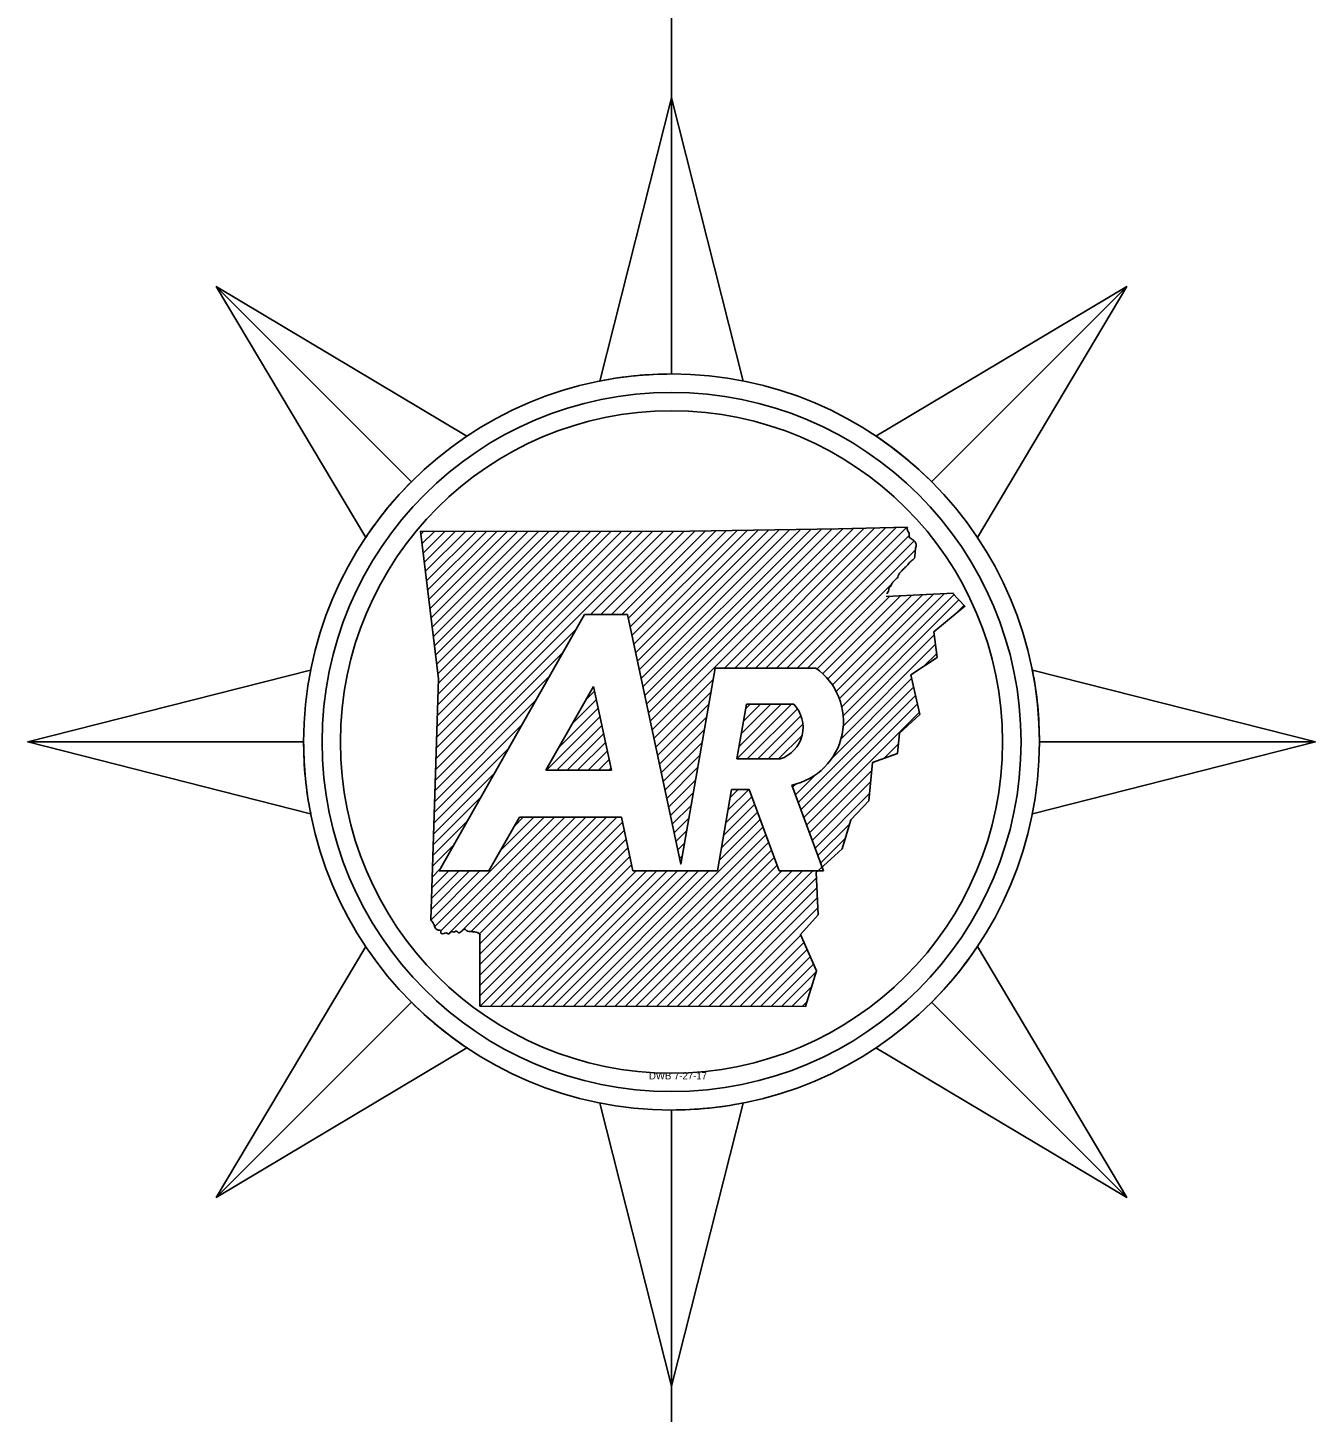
# Model space of a CAD drawing. Extents: x 155 to 3386, y 68 to 2138.
# Drawn here: x 2378.1 to 2518.1, y 610.2 to 760.7 of the extents above; entities that cross this region are included whole.
import ezdxf

# ---------------------------------------------------------------- set-up
doc = ezdxf.new("R2010")
doc.units = 0
doc.layers.add('R_Draft', color=7, linetype='Continuous')

msp = doc.modelspace()

# ---------------------------------------------------------------- linework, layer by layer
at = {"layer": 'R_Draft'}
for p, q in [((2448.14, 885.31), (2448.14, 727.4)), ((2448.14, 753.03), (2440.35, 722.26)), ((2448.14, 723.03), (2448.14, 753.03)), ((2398.64, 732.53), (2419.85, 711.31)), ((2419.85, 711.31), (2398.64, 732.53)), ((2398.64, 732.53), (2414.89, 705.26)), ((2497.63, 732.53), (2470.37, 716.28)), ((2476.42, 711.31), (2497.63, 732.53)), ((2476.42, 711.31), (2497.63, 732.53)), ((2420.87, 705.57), (2421.22, 705.93)), ((2421, 704.57), (2422.35, 705.92)), ((2421.12, 703.56), (2423.48, 705.92)), ((2421.25, 702.55), (2424.62, 705.92)), ((2421.37, 701.55), (2425.75, 705.92)), ((2421.5, 700.54), (2426.88, 705.92)), ((2421.62, 699.54), (2428.01, 705.92)), ((2421.75, 698.53), (2429.14, 705.92)), ((2421.87, 697.52), (2430.27, 705.92)), ((2422, 696.52), (2431.4, 705.92)), ((2422.12, 695.51), (2432.53, 705.92)), ((2422.25, 694.51), (2433.66, 705.92)), ((2422.37, 693.5), (2434.79, 705.92)), ((2422.5, 692.49), (2435.92, 705.92)), ((2422.54, 681.22), (2447.26, 705.94)), ((2422.58, 682.39), (2446.12, 705.94)), ((2422.62, 683.56), (2444.99, 705.93)), ((2422.62, 691.49), (2437.05, 705.92)), ((2422.65, 684.73), (2443.86, 705.93)), ((2422.69, 685.9), (2442.72, 705.93)), ((2422.73, 687.07), (2441.59, 705.93)), ((2422.75, 690.48), (2438.19, 705.92)), ((2422.77, 688.24), (2440.46, 705.92)), ((2422.81, 689.41), (2439.32, 705.92)), ((2439.34, 696.89), (2448.39, 705.94)), ((2440.47, 696.89), (2449.53, 705.94)), ((2441.6, 696.89), (2450.67, 705.95)), ((2442.73, 696.89), (2451.82, 705.97)), ((2443.44, 696.46), (2452.97, 705.99)), ((2443.64, 695.53), (2454.11, 706.01)), ((2443.84, 694.6), (2455.26, 706.02)), ((2444.04, 693.66), (2456.41, 706.04)), ((2444.23, 692.73), (2457.56, 706.06)), ((2444.43, 691.8), (2458.71, 706.08)), ((2444.63, 690.87), (2459.86, 706.1)), ((2444.83, 689.94), (2461.01, 706.11)), ((2445.03, 689.01), (2462.16, 706.13)), ((2445.23, 688.07), (2463.31, 706.15)), ((2445.43, 687.14), (2464.46, 706.17)), ((2445.63, 686.21), (2465.61, 706.19)), ((2445.83, 685.28), (2466.76, 706.21)), ((2446.03, 684.35), (2467.92, 706.23)), ((2453.89, 691.07), (2469.08, 706.26)), ((2455.02, 691.07), (2470.23, 706.29)), ((2456.15, 691.07), (2471.39, 706.31)), ((2457.28, 691.07), (2472.55, 706.34)), ((2458.41, 691.07), (2473.71, 706.37)), ((2459.55, 691.07), (2473.96, 705.49)), ((2460.68, 691.07), (2474.51, 704.9)), ((2461.81, 691.07), (2474.65, 703.92)), ((2462.94, 691.07), (2472.07, 700.2)), ((2463.97, 690.97), (2471.85, 698.85)), ((2464.59, 690.46), (2473.04, 698.91)), ((2465.14, 689.88), (2474.23, 698.97)), ((2465.63, 689.23), (2475.43, 699.03)), ((2466.05, 688.52), (2476.62, 699.1)), ((2466.39, 687.74), (2477.81, 699.16)), ((2466.65, 686.87), (2478.89, 699.1)), ((2466.81, 685.89), (2479.41, 698.5)), ((2422.87, 669.02), (2438.66, 696.89)), ((2438.66, 696.89), (2443.35, 696.89)), ((2478.91, 696.86), (2479.94, 697.89)), ((2422.5, 680.05), (2437.76, 695.31)), ((2466.81, 684.76), (2476.71, 694.67)), ((2422.46, 678.88), (2436.29, 692.71)), ((2466.58, 683.39), (2476.84, 693.66)), ((2475.58, 691.27), (2476.97, 692.66)), ((2452.87, 691.07), (2463.83, 691.07)), ((2518.14, 683.03), (2487.37, 690.82)), ((2422.42, 677.71), (2434.81, 690.1)), ((2446.23, 683.41), (2452.65, 689.83)), ((2465.59, 681.28), (2474.24, 689.92)), ((2434.48, 679.96), (2439.65, 689.07)), ((2438.84, 687.65), (2439.75, 688.57)), ((2446.43, 682.48), (2452.41, 688.46)), ((2461.9, 676.46), (2474.45, 689)), ((2462.21, 675.64), (2474.66, 688.08)), ((2422.38, 676.54), (2433.33, 687.49)), ((2435.89, 682.44), (2440.15, 686.7)), ((2437.37, 685.05), (2439.95, 687.63)), ((2446.63, 681.55), (2452.17, 687.09)), ((2455.25, 681.19), (2461.2, 687.14)), ((2455.48, 682.55), (2460.07, 687.14)), ((2455.72, 683.92), (2458.94, 687.14)), ((2455.96, 685.29), (2457.81, 687.14)), ((2456.2, 686.66), (2456.68, 687.14)), ((2456.28, 687.14), (2461.43, 687.14)), ((2456.38, 681.19), (2461.83, 686.64)), ((2462.52, 674.81), (2474.87, 687.16)), ((2422.34, 675.37), (2431.86, 684.88)), ((2434.54, 679.96), (2440.35, 685.77)), ((2435.67, 679.96), (2440.55, 684.84)), ((2446.83, 680.62), (2451.93, 685.72)), ((2457.51, 681.19), (2462.21, 685.89)), ((2458.64, 681.19), (2462.42, 684.97)), ((2462.82, 673.98), (2475.08, 686.24)), ((2436.8, 679.96), (2440.75, 683.91)), ((2447.03, 679.69), (2451.69, 684.35)), ((2459.78, 681.19), (2462.33, 683.74)), ((2378.14, 683.03), (2408.14, 683.03)), ((2408.14, 683.03), (2378.14, 683.03)), ((2378.14, 683.03), (2408.9, 675.24)), ((2422.3, 674.2), (2430.38, 682.27)), ((2437.93, 679.96), (2440.95, 682.97)), ((2439.06, 679.96), (2441.15, 682.04)), ((2447.23, 678.75), (2451.46, 682.98)), ((2471.22, 681.25), (2472.8, 682.83)), ((2488.14, 683.03), (2518.14, 683.03)), ((2488.14, 683.03), (2518.14, 683.03)), ((2440.19, 679.96), (2441.35, 681.11)), ((2447.43, 677.82), (2451.22, 681.61)), ((2447.63, 676.89), (2450.98, 680.24)), ((2455.24, 681.19), (2459.94, 681.19)), ((2422.27, 673.03), (2428.9, 679.66)), ((2434.48, 679.96), (2441.6, 679.96)), ((2441.33, 679.96), (2441.55, 680.18)), ((2447.82, 675.96), (2450.74, 678.87)), ((2461.6, 677.29), (2463.75, 679.44)), ((2463.13, 673.16), (2469.91, 679.94)), ((2448.02, 675.03), (2450.5, 677.5)), ((2454.27, 675.62), (2456.53, 677.88)), ((2454.51, 676.99), (2455.4, 677.88)), ((2456.57, 677.88), (2454.67, 677.88)), ((2459.84, 669.02), (2456.57, 677.88)), ((2461.21, 678.35), (2464.66, 669.02)), ((2461.29, 678.11), (2461.64, 678.46)), ((2463.43, 672.33), (2469.79, 678.69)), ((2463.74, 671.5), (2469.66, 677.43)), ((2422.23, 671.86), (2427.43, 677.06)), ((2448.22, 674.09), (2450.26, 676.13)), ((2453.8, 672.88), (2457.17, 676.25)), ((2454.03, 674.25), (2456.86, 677.08)), ((2422.19, 670.69), (2425.95, 674.45)), ((2422.39, 662.97), (2434.29, 674.86)), ((2423.07, 662.51), (2435.42, 674.86)), ((2423.88, 662.19), (2436.55, 674.86)), ((2425.22, 662.41), (2437.68, 674.86)), ((2426.37, 662.43), (2438.81, 674.86)), ((2427.26, 662.18), (2439.94, 674.86)), ((2427.3, 659.96), (2442.2, 674.86)), ((2427.3, 661.09), (2441.07, 674.86)), ((2427.3, 658.83), (2442.8, 674.33)), ((2431.6, 674.86), (2428.29, 669.02)), ((2429.57, 671.28), (2433.15, 674.86)), ((2431.05, 673.89), (2432.02, 674.86)), ((2442.69, 674.86), (2431.6, 674.86)), ((2448.42, 673.16), (2450.02, 674.76)), ((2453.32, 670.14), (2457.78, 674.6)), ((2453.56, 671.51), (2457.47, 675.42)), ((2427.31, 657.7), (2443, 673.4)), ((2438.62, 654.31), (2458.08, 673.77)), ((2439.75, 654.31), (2458.39, 672.95)), ((2448.62, 672.23), (2449.78, 673.39)), ((2464.04, 670.68), (2467.51, 674.15)), ((2422.15, 669.52), (2424.47, 671.84)), ((2427.31, 656.57), (2443.2, 672.46)), ((2427.31, 655.44), (2443.4, 671.53)), ((2440.88, 654.31), (2458.69, 672.12)), ((2442.01, 654.31), (2459, 671.29)), ((2448.82, 671.3), (2449.54, 672.02)), ((2464.35, 669.85), (2467.03, 672.53)), ((2427.33, 654.33), (2443.6, 670.6)), ((2443.14, 654.31), (2459.31, 670.47)), ((2449.02, 670.37), (2449.31, 670.65)), ((2421.97, 663.68), (2427.31, 669.02)), ((2421.99, 664.83), (2426.17, 669.02)), ((2422.03, 666.01), (2425.04, 669.02)), ((2422.07, 667.18), (2423.91, 669.02)), ((2422.11, 668.35), (2423, 669.23)), ((2428.29, 669.02), (2422.87, 669.02)), ((2428.46, 654.33), (2443.8, 669.67)), ((2429.59, 654.33), (2444.28, 669.02)), ((2430.72, 654.33), (2445.41, 669.02)), ((2431.85, 654.32), (2446.54, 669.02)), ((2432.98, 654.32), (2447.67, 669.02)), ((2434.11, 654.32), (2448.8, 669.02)), ((2435.24, 654.32), (2449.93, 669.02)), ((2436.37, 654.32), (2451.06, 669.02)), ((2437.5, 654.31), (2452.2, 669.02)), ((2453.12, 669.02), (2443.94, 669.02)), ((2444.27, 654.3), (2459.61, 669.64)), ((2445.4, 654.3), (2460.12, 669.02)), ((2446.53, 654.3), (2461.25, 669.02)), ((2447.66, 654.3), (2462.38, 669.02)), ((2448.79, 654.3), (2463.51, 669.02)), ((2449.92, 654.29), (2463.89, 668.26)), ((2464.66, 669.02), (2459.84, 669.02)), ((2451.05, 654.29), (2463.94, 667.18)), ((2452.18, 654.29), (2463.99, 666.1)), ((2453.31, 654.29), (2464.04, 665.02)), ((2454.44, 654.29), (2462.18, 662.03)), ((2455.57, 654.29), (2462.53, 661.25)), ((2497.63, 633.53), (2481.39, 660.79)), ((2456.7, 654.28), (2462.88, 660.47)), ((2457.83, 654.28), (2463.23, 659.68)), ((2458.96, 654.28), (2463.58, 658.9)), ((2460.09, 654.28), (2463.87, 658.06)), ((2461.22, 654.28), (2463.36, 656.42)), ((2398.64, 633.53), (2419.85, 654.74)), ((2419.85, 654.74), (2398.64, 633.53)), ((2462.34, 654.27), (2462.85, 654.78)), ((2476.42, 654.74), (2497.63, 633.53)), ((2476.42, 654.74), (2497.63, 633.53)), ((2398.64, 633.53), (2425.9, 649.78)), ((2448.13, 643.03), (2448.14, 643.03)), ((2448.14, 613.03), (2455.93, 643.79)), ((2448.14, 643.03), (2448.14, 514.98)), ((2448.14, 643.03), (2448.14, 613.03))]:
    msp.add_line(p, q, dxfattribs=at)
for points in [[(2440.35, 722.26), (2448.14, 753.03), (2455.93, 722.26)], [(2414.89, 705.26), (2398.64, 732.53), (2425.9, 716.28)], [(2470.37, 716.28), (2497.63, 732.53), (2481.39, 705.26)], [(2420.83, 705.93), (2436.44, 705.92), (2450.13, 705.94), (2466.29, 706.2), (2473.78, 706.37)], [(2421.96, 663.69), (2422.82, 689.88), (2420.83, 705.93)], [(2478.69, 699.2), (2480.04, 697.79), (2476.67, 695.02), (2477.03, 692.22), (2474.14, 690.32), (2475.13, 686.02), (2472.91, 683.99), (2472.71, 681.78), (2470, 680.81), (2469.58, 676.64), (2467.63, 674.56), (2466.69, 671.42), (2463.86, 668.83), (2464.08, 664.26), (2462.15, 662.1), (2463.91, 658.17), (2462.69, 654.27)], [(2471.46, 698.83), (2478.79, 699.21)], [(2443.35, 696.89), (2449.15, 669.76), (2452.87, 691.07)], [(2408.9, 675.24), (2378.14, 683.03), (2408.9, 690.82)], [(2487.37, 690.82), (2518.14, 683.03), (2487.37, 675.24)], [(2439.65, 689.07), (2441.6, 679.96)], [(2455.24, 681.19), (2456.28, 687.14)], [(2454.67, 677.88), (2453.12, 669.02)], [(2443.94, 669.02), (2442.69, 674.86)], [(2425.9, 649.78), (2398.64, 633.53), (2414.89, 660.79)], [(2462.69, 654.27), (2427.31, 654.33), (2427.29, 662.14)], [(2481.39, 660.79), (2497.63, 633.53), (2470.37, 649.78)], [(2455.93, 643.79), (2448.14, 613.03), (2440.35, 643.79)]]:
    msp.add_lwpolyline(points, dxfattribs=at)
for radius in [40, 38, 36]:
    msp.add_circle((2448.14, 683.03), radius, dxfattribs=at)
for centre, radius, start, end in [((2448.14, 683.03), 40, 90, 101.2291), ((2448.14, 683.03), 40, 45, 56.2291), ((2448.14, 683.03), 40, 135, 146.2291), ((2459.75, 685.28), 7.08, 281.8626, 54.8705), ((2448.14, 683.03), 40, 0, 11.2291), ((2458.82, 684.63), 3.62, 288.1268, 43.8902), ((2448.14, 683.03), 40, 180, 191.2291), ((2448.14, 683.03), 40, 315, 326.2291), ((2448.14, 683.03), 40, 225, 236.2291), ((2448.14, 683.03), 40, 270, 281.2291)]:
    msp.add_arc(centre, radius, start, end, dxfattribs=at)
for points in [[(2473.78, 706.37), (2473.83, 705.94), (2473.97, 705.72), (2473.98, 705.32), (2474.15, 705.14), (2474.43, 704.97), (2474.68, 704.69), (2474.74, 704.36), (2474.66, 704.02), (2474.64, 703.65), (2474.6, 703.32), (2474.54, 703.02), (2474.31, 702.78), (2474.09, 702.6), (2473.89, 702.4), (2473.74, 702.19), (2473.49, 701.96), (2473.24, 701.72), (2473.04, 701.5), (2472.84, 701.23), (2472.74, 700.94), (2472.52, 700.72), (2472.34, 700.53), (2472.11, 700.27), (2472, 700.01), (2471.77, 699.71), (2471.73, 699.42), (2471.58, 699.19), (2471.57, 699.15)], [(2427.29, 662.14), (2427.33, 662.12), (2427.15, 662.25), (2426.9, 662.37), (2426.62, 662.39), (2426.26, 662.44), (2425.96, 662.47), (2425.65, 662.67), (2425.32, 662.46), (2424.96, 662.3), (2424.75, 662.48), (2424.47, 662.36), (2424.27, 662.42), (2423.93, 662.19), (2423.62, 662.28), (2423.38, 662.21), (2423.1, 662.22), (2423.04, 662.55), (2422.76, 662.59), (2422.52, 662.73), (2422.35, 663.07), (2422.24, 663.33), (2421.96, 663.69)]]:
    msp.add_spline(points, degree=3, dxfattribs=at)

# ---------------------------------------------------------------- texts
msp.add_text('DWB 7-27-17', height=0.7778, dxfattribs=at).set_placement((2445.69, 646.36))

doc.saveas('drawing.dxf')
